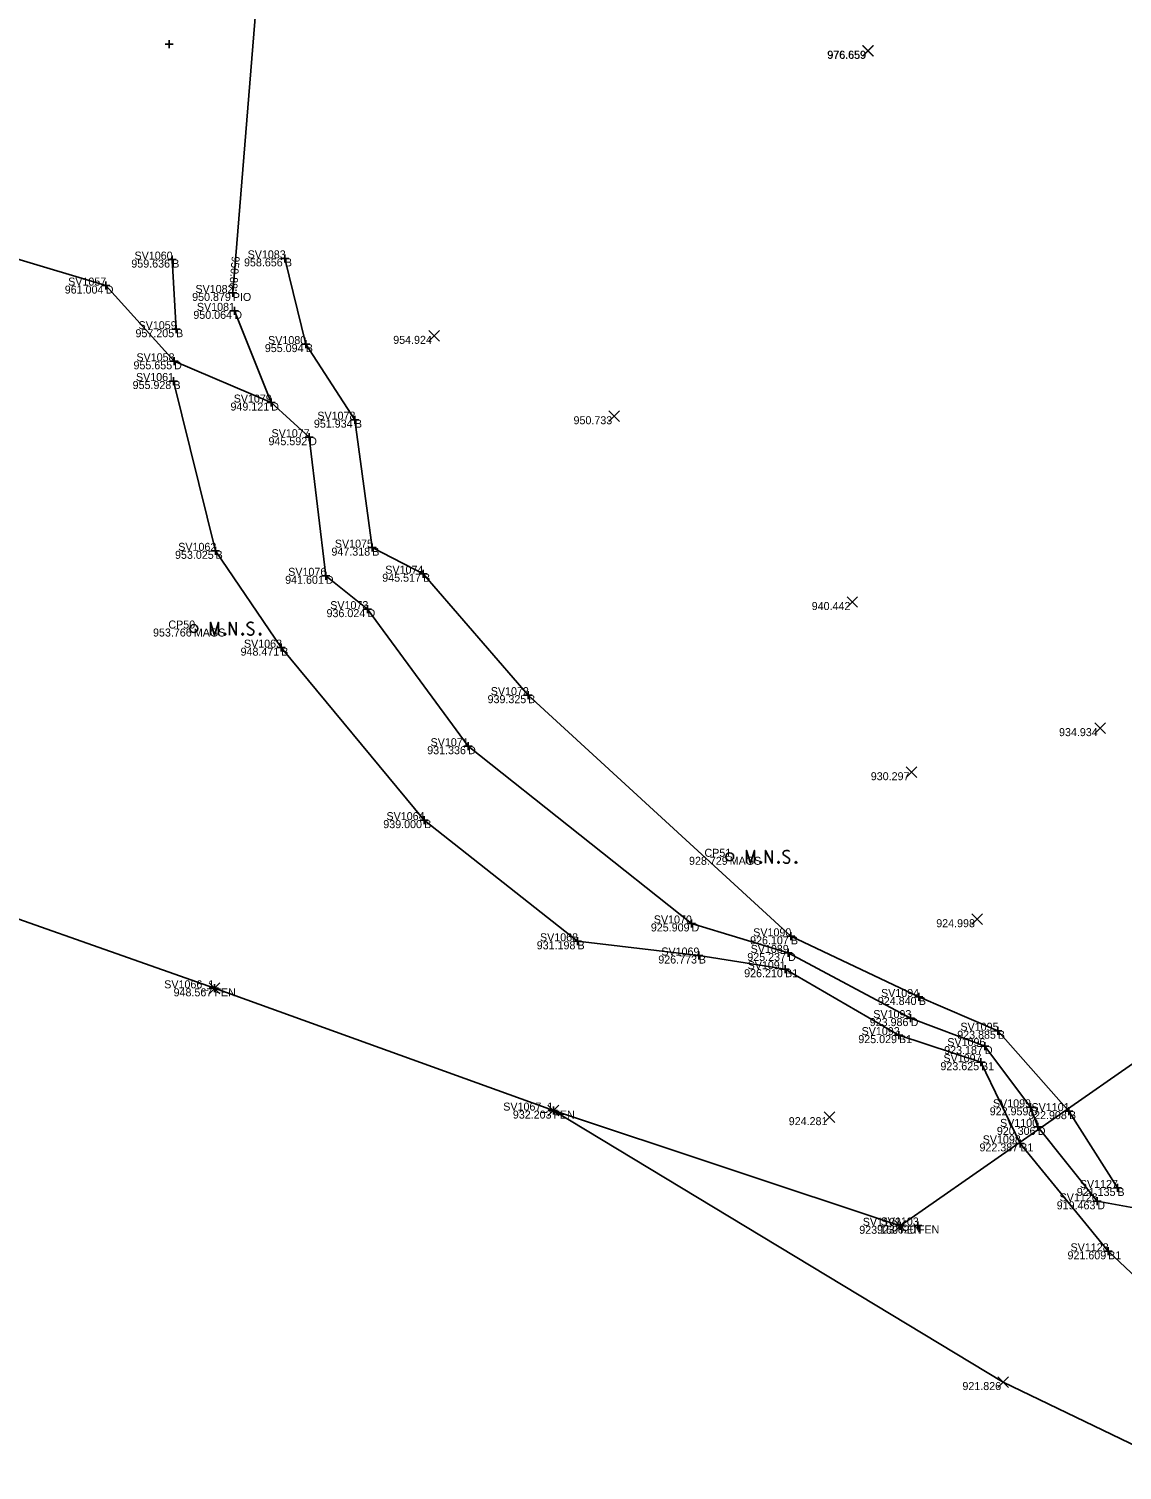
# Model space of a CAD drawing. Extents: x 2065431 to 2068157, y 709104 to 709719.
# Drawn here: x 2067117.5 to 2067254.1, y 709104.9 to 709285 of the extents above; entities that cross this region are included whole.
import ezdxf

# ---------------------------------------------------------------- set-up
doc = ezdxf.new("R2010")
doc.units = 0
for name, color, linetype in [('_CIVIL_CONSTRUCTION', 7, 'Continuous'), ('DR_X_Storm_Sewer', 7, 'Continuous'), ('DT_X_Terrain_Boundary', 7, 'Continuous'), ('RD_X_Fence', 7, 'Continuous'), ('RS_Raster1', 7, 'Continuous'), ('RW_X_CL_100_Bearings', 7, 'Continuous'), ('RW_X_CL_100_Curve_Data', 7, 'Continuous'), ('RW_X_Fee_WL', 7, 'Continuous'), ('SC_Scratch1', 7, 'Continuous'), ('SV_X_Break_Lines', 7, 'Continuous'), ('SV_X_Mon_Cells_Found', 7, 'Continuous'), ('SV_X_Text_Elevation', 7, 'Continuous'), ('SV_X_Text_Name', 7, 'Continuous')]:
    doc.layers.add(name, color=color, linetype=linetype)

msp = doc.modelspace()

# ---------------------------------------------------------------- linework, layer by layer
at = {"layer": '_CIVIL_CONSTRUCTION'}
for p, q in [((2067142.47, 709251.99), (2067143.47, 709251.99)), ((2067142.97, 709252.49), (2067142.97, 709251.49)), ((2067142.97, 709251.99), (2067142.97, 709251.99))]:
    msp.add_line(p, q, dxfattribs=at)
at = {"layer": 'DR_X_Storm_Sewer'}
msp.add_line((2067152.25, 709366.82), (2067142.97, 709251.99), dxfattribs=at)
at = {"layer": 'DT_X_Terrain_Boundary'}
msp.add_lwpolyline([(2067102.37, 709178.61), (2067140.67, 709165.08), (2067183.02, 709149.8), (2067239.23, 709115.87), (2067261.89, 709104.93), (2067274.06, 709104.86), (2067277.37, 709106.22), (2067284.73, 709107.64), (2067304.22, 709108.67), (2067329.31, 709129.97), (2067346.3, 709160.09), (2067342.01, 709185.45), (2067370.56, 709268.21), (2067411.97, 709264.45), (2067464.57, 709259.36), (2067538.62, 709266.34)], dxfattribs=at)
at = {"layer": 'RD_X_Fence'}
msp.add_line((2067226.35, 709135.4), (2067267.15, 709163.89), dxfattribs=at)
msp.add_lwpolyline([(2067064.4, 709192.69), (2067102.37, 709178.61), (2067140.67, 709165.08), (2067183.02, 709149.8), (2067226.35, 709135.4)], dxfattribs=at)
at = {"layer": 'RS_Raster1'}
for p, q in [((2067134.5, 709283.08), (2067135.5, 709283.08)), ((2067135, 709283.58), (2067135, 709282.58)), ((2067135, 709283.08), (2067135, 709283.08)), ((2067134.9, 709256.16), (2067135.9, 709256.16)), ((2067135.4, 709256.66), (2067135.4, 709255.66)), ((2067135.4, 709256.16), (2067135.4, 709256.16)), ((2067148.98, 709256.31), (2067149.98, 709256.31)), ((2067149.48, 709256.81), (2067149.48, 709255.81)), ((2067149.48, 709256.31), (2067149.48, 709256.31)), ((2067127.09, 709253.41), (2067127.09, 709252.41)), ((2067126.59, 709252.91), (2067127.59, 709252.91)), ((2067127.09, 709252.91), (2067127.09, 709252.91)), ((2067142.66, 709249.75), (2067143.66, 709249.75)), ((2067143.16, 709250.25), (2067143.16, 709249.25)), ((2067143.16, 709249.75), (2067143.16, 709249.75)), ((2067135.88, 709247.96), (2067135.88, 709246.96)), ((2067135.38, 709247.46), (2067136.38, 709247.46)), ((2067135.88, 709247.46), (2067135.88, 709247.46)), ((2067151.59, 709245.6), (2067152.59, 709245.6)), ((2067152.09, 709246.1), (2067152.09, 709245.1)), ((2067152.09, 709245.6), (2067152.09, 709245.6)), ((2067135.13, 709243.45), (2067136.13, 709243.45)), ((2067135.63, 709243.95), (2067135.63, 709242.95)), ((2067135.63, 709243.45), (2067135.63, 709243.45)), ((2067135.05, 709240.98), (2067136.05, 709240.98)), ((2067135.55, 709241.48), (2067135.55, 709240.48)), ((2067135.55, 709240.98), (2067135.55, 709240.98)), ((2067147.26, 709238.29), (2067148.26, 709238.29)), ((2067147.76, 709238.79), (2067147.76, 709237.79)), ((2067147.76, 709238.29), (2067147.76, 709238.29)), ((2067157.72, 709236.15), (2067158.72, 709236.15)), ((2067158.22, 709236.65), (2067158.22, 709235.65)), ((2067158.22, 709236.15), (2067158.22, 709236.15)), ((2067152.01, 709233.96), (2067153.01, 709233.96)), ((2067152.51, 709234.46), (2067152.51, 709233.46)), ((2067152.51, 709233.96), (2067152.51, 709233.96)), ((2067140.32, 709219.76), (2067141.32, 709219.76)), ((2067140.82, 709220.26), (2067140.82, 709219.26)), ((2067140.82, 709219.76), (2067140.82, 709219.76)), ((2067159.89, 709220.16), (2067160.89, 709220.16)), ((2067160.39, 709220.66), (2067160.39, 709219.66)), ((2067160.39, 709220.16), (2067160.39, 709220.16)), ((2067166.74, 709217.4), (2067166.74, 709216.4)), ((2067154.09, 709216.64), (2067155.09, 709216.64)), ((2067154.59, 709217.14), (2067154.59, 709216.14)), ((2067154.59, 709216.64), (2067154.59, 709216.64)), ((2067166.24, 709216.9), (2067167.24, 709216.9)), ((2067166.74, 709216.9), (2067166.74, 709216.9)), ((2067159.3, 709212.47), (2067160.3, 709212.47)), ((2067159.8, 709212.97), (2067159.8, 709211.97)), ((2067159.8, 709212.47), (2067159.8, 709212.47)), ((2067148.52, 709207.66), (2067149.52, 709207.66)), ((2067149.02, 709208.16), (2067149.02, 709207.16)), ((2067149.02, 709207.66), (2067149.02, 709207.66)), ((2067179.37, 709201.72), (2067180.37, 709201.72)), ((2067179.87, 709202.22), (2067179.87, 709201.22)), ((2067179.87, 709201.72), (2067179.87, 709201.72)), ((2067172.36, 709195.84), (2067172.36, 709194.84)), ((2067171.86, 709195.34), (2067172.86, 709195.34)), ((2067172.36, 709195.34), (2067172.36, 709195.34)), ((2067166.39, 709186.1), (2067167.39, 709186.1)), ((2067166.89, 709186.6), (2067166.89, 709185.6)), ((2067166.89, 709186.1), (2067166.89, 709186.1)), ((2067199.78, 709173.19), (2067200.78, 709173.19)), ((2067200.28, 709173.69), (2067200.28, 709172.69)), ((2067200.28, 709173.19), (2067200.28, 709173.19)), ((2067185.54, 709170.96), (2067186.54, 709170.96)), ((2067186.04, 709171.46), (2067186.04, 709170.46)), ((2067186.04, 709170.96), (2067186.04, 709170.96)), ((2067212.2, 709171.58), (2067213.2, 709171.58)), ((2067212.7, 709172.08), (2067212.7, 709171.08)), ((2067212.7, 709171.58), (2067212.7, 709171.58)), ((2067200.69, 709169.18), (2067201.69, 709169.18)), ((2067201.19, 709169.68), (2067201.19, 709168.68)), ((2067201.19, 709169.18), (2067201.19, 709169.18)), ((2067211.85, 709169.5), (2067212.85, 709169.5)), ((2067212.35, 709170), (2067212.35, 709169)), ((2067212.35, 709169.5), (2067212.35, 709169.5)), ((2067211.47, 709167.47), (2067212.47, 709167.47)), ((2067211.97, 709167.97), (2067211.97, 709166.97)), ((2067211.97, 709167.47), (2067211.97, 709167.47)), ((2067140.17, 709165.08), (2067141.17, 709165.08)), ((2067140.67, 709165.58), (2067140.67, 709164.58)), ((2067140.67, 709165.08), (2067140.67, 709165.08)), ((2067228.18, 709164), (2067229.18, 709164)), ((2067228.68, 709164.5), (2067228.68, 709163.5)), ((2067228.68, 709164), (2067228.68, 709164)), ((2067227.66, 709161.86), (2067227.66, 709160.86)), ((2067226.2, 709159.73), (2067226.2, 709158.73)), ((2067227.16, 709161.36), (2067228.16, 709161.36)), ((2067227.66, 709161.36), (2067227.66, 709161.36)), ((2067238.05, 709159.78), (2067239.05, 709159.78)), ((2067238.55, 709160.28), (2067238.55, 709159.28)), ((2067238.55, 709159.78), (2067238.55, 709159.78)), ((2067225.7, 709159.23), (2067226.7, 709159.23)), ((2067226.2, 709159.23), (2067226.2, 709159.23)), ((2067236.44, 709157.86), (2067237.44, 709157.86)), ((2067236.94, 709158.36), (2067236.94, 709157.36)), ((2067236.94, 709157.86), (2067236.94, 709157.86)), ((2067236.45, 709156.35), (2067236.45, 709155.35)), ((2067235.95, 709155.85), (2067236.95, 709155.85)), ((2067236.45, 709155.85), (2067236.45, 709155.85)), ((2067242.62, 709150.71), (2067242.62, 709149.71)), ((2067182.52, 709149.8), (2067183.52, 709149.8)), ((2067183.02, 709150.3), (2067183.02, 709149.3)), ((2067183.02, 709149.8), (2067183.02, 709149.8)), ((2067242.12, 709150.21), (2067243.12, 709150.21)), ((2067242.62, 709150.21), (2067242.62, 709150.21)), ((2067246.94, 709149.73), (2067247.94, 709149.73)), ((2067247.44, 709150.23), (2067247.44, 709149.23)), ((2067247.44, 709149.73), (2067247.44, 709149.73)), ((2067243.04, 709147.76), (2067244.04, 709147.76)), ((2067243.54, 709148.26), (2067243.54, 709147.26)), ((2067243.54, 709147.76), (2067243.54, 709147.76)), ((2067240.86, 709145.7), (2067241.86, 709145.7)), ((2067241.36, 709146.2), (2067241.36, 709145.2)), ((2067241.36, 709145.7), (2067241.36, 709145.7)), ((2067252.99, 709140.13), (2067253.99, 709140.13)), ((2067253.49, 709140.63), (2067253.49, 709139.63)), ((2067253.49, 709140.13), (2067253.49, 709140.13)), ((2067250.48, 709138.46), (2067251.48, 709138.46)), ((2067250.98, 709138.96), (2067250.98, 709137.96)), ((2067250.98, 709138.46), (2067250.98, 709138.46)), ((2067225.85, 709135.4), (2067226.85, 709135.4)), ((2067225.85, 709135.4), (2067226.85, 709135.4)), ((2067226.35, 709135.9), (2067226.35, 709134.9)), ((2067226.35, 709135.9), (2067226.35, 709134.9)), ((2067226.35, 709135.4), (2067226.35, 709135.4)), ((2067226.35, 709135.4), (2067226.35, 709135.4)), ((2067228.07, 709135.44), (2067229.07, 709135.44)), ((2067228.57, 709135.94), (2067228.57, 709134.94)), ((2067228.57, 709135.44), (2067228.57, 709135.44)), ((2067252.34, 709132.71), (2067252.34, 709131.71)), ((2067251.84, 709132.21), (2067252.84, 709132.21)), ((2067252.34, 709132.21), (2067252.34, 709132.21))]:
    msp.add_line(p, q, dxfattribs=at)
at = {"layer": 'RW_X_CL_100_Bearings'}
for p, q in [((2067221.65, 709281.6), (2067222.98, 709282.93)), ((2067221.65, 709282.93), (2067222.98, 709281.6)), ((2067221.69, 709281.57), (2067223.02, 709282.91)), ((2067221.69, 709282.91), (2067223.02, 709281.57)), ((2067167.46, 709245.96), (2067168.8, 709247.3)), ((2067167.46, 709247.3), (2067168.8, 709245.96)), ((2067189.94, 709235.91), (2067191.27, 709237.25)), ((2067189.94, 709237.25), (2067191.27, 709235.91)), ((2067219.71, 709212.7), (2067221.04, 709214.03)), ((2067219.71, 709214.03), (2067221.04, 709212.7)), ((2067250.66, 709196.93), (2067251.99, 709198.27)), ((2067250.66, 709198.27), (2067251.99, 709196.93)), ((2067227.11, 709191.42), (2067228.44, 709192.75)), ((2067227.11, 709192.75), (2067228.44, 709191.42)), ((2067235.29, 709173.05), (2067236.63, 709174.39)), ((2067235.29, 709174.39), (2067236.63, 709173.05)), ((2067140, 709164.41), (2067141.33, 709165.75)), ((2067140, 709165.75), (2067141.33, 709164.41)), ((2067182.35, 709149.13), (2067183.69, 709150.47)), ((2067182.35, 709150.47), (2067183.69, 709149.13)), ((2067216.84, 709148.31), (2067218.17, 709149.65)), ((2067216.84, 709149.65), (2067218.17, 709148.31)), ((2067225.69, 709134.73), (2067227.02, 709136.06)), ((2067225.69, 709136.06), (2067227.02, 709134.73)), ((2067238.57, 709115.2), (2067239.9, 709116.53)), ((2067238.57, 709116.53), (2067239.9, 709115.2))]:
    msp.add_line(p, q, dxfattribs=at)
at = {"layer": 'RW_X_CL_100_Curve_Data'}
for points in [[(2067140.19, 709209.24), (2067140.19, 709210.84), (2067140.7, 709209.24), (2067141.18, 709210.84), (2067141.18, 709209.24)], [(2067142.56, 709209.24), (2067142.56, 709210.84), (2067143.39, 709209.24), (2067143.39, 709210.84)], [(2067145.54, 709210.73), (2067145.51, 709210.76), (2067145.48, 709210.78), (2067145.38, 709210.82), (2067145.26, 709210.84), (2067145.17, 709210.84), (2067145.14, 709210.84), (2067145, 709210.81), (2067144.88, 709210.73), (2067144.8, 709210.63), (2067144.78, 709210.53), (2067144.78, 709210.45), (2067144.8, 709210.35), (2067144.89, 709210.26), (2067145.49, 709209.89), (2067145.55, 709209.84), (2067145.57, 709209.79), (2067145.59, 709209.71), (2067145.59, 709209.64), (2067145.58, 709209.56), (2067145.57, 709209.51), (2067145.55, 709209.45), (2067145.53, 709209.4), (2067145.5, 709209.36), (2067145.47, 709209.32), (2067145.44, 709209.29), (2067145.39, 709209.27), (2067145.36, 709209.26), (2067145.26, 709209.24), (2067145.11, 709209.24), (2067145.01, 709209.27), (2067144.86, 709209.36), (2067144.78, 709209.43)], [(2067141.95, 709209.46), (2067142.01, 709209.46), (2067142.04, 709209.43), (2067142.08, 709209.38), (2067142.08, 709209.32), (2067142.04, 709209.27), (2067142.01, 709209.24), (2067141.95, 709209.24), (2067141.92, 709209.27), (2067141.89, 709209.32), (2067141.89, 709209.38), (2067141.92, 709209.43), (2067141.95, 709209.46)], [(2067144.17, 709209.46), (2067144.22, 709209.46), (2067144.26, 709209.43), (2067144.29, 709209.38), (2067144.29, 709209.32), (2067144.26, 709209.27), (2067144.22, 709209.24), (2067144.17, 709209.24), (2067144.14, 709209.27), (2067144.1, 709209.32), (2067144.1, 709209.38), (2067144.14, 709209.43), (2067144.17, 709209.46)], [(2067146.35, 709209.46), (2067146.41, 709209.46), (2067146.44, 709209.43), (2067146.47, 709209.38), (2067146.47, 709209.32), (2067146.44, 709209.27), (2067146.41, 709209.24), (2067146.35, 709209.24), (2067146.32, 709209.27), (2067146.29, 709209.32), (2067146.29, 709209.38), (2067146.32, 709209.43), (2067146.35, 709209.46)], [(2067207.14, 709180.72), (2067207.14, 709182.32), (2067207.65, 709180.72), (2067208.13, 709182.32), (2067208.13, 709180.72)], [(2067209.51, 709180.72), (2067209.51, 709182.32), (2067210.34, 709180.72), (2067210.34, 709182.32)], [(2067212.49, 709182.2), (2067212.47, 709182.23), (2067212.43, 709182.25), (2067212.33, 709182.29), (2067212.21, 709182.32), (2067212.12, 709182.32), (2067212.09, 709182.32), (2067211.95, 709182.28), (2067211.83, 709182.2), (2067211.75, 709182.1), (2067211.73, 709182), (2067211.73, 709181.92), (2067211.75, 709181.82), (2067211.84, 709181.74), (2067212.44, 709181.36), (2067212.5, 709181.31), (2067212.52, 709181.26), (2067212.54, 709181.18), (2067212.54, 709181.11), (2067212.53, 709181.03), (2067212.52, 709180.98), (2067212.5, 709180.92), (2067212.48, 709180.87), (2067212.46, 709180.83), (2067212.42, 709180.79), (2067212.39, 709180.77), (2067212.35, 709180.74), (2067212.31, 709180.73), (2067212.21, 709180.72), (2067212.06, 709180.72), (2067211.96, 709180.74), (2067211.82, 709180.83), (2067211.73, 709180.9)], [(2067208.91, 709180.93), (2067208.96, 709180.93), (2067208.99, 709180.9), (2067209.03, 709180.85), (2067209.03, 709180.79), (2067208.99, 709180.74), (2067208.96, 709180.72), (2067208.91, 709180.72), (2067208.87, 709180.74), (2067208.84, 709180.79), (2067208.84, 709180.85), (2067208.87, 709180.9), (2067208.91, 709180.93)], [(2067211.12, 709180.93), (2067211.18, 709180.93), (2067211.21, 709180.9), (2067211.24, 709180.85), (2067211.24, 709180.79), (2067211.21, 709180.74), (2067211.18, 709180.72), (2067211.12, 709180.72), (2067211.09, 709180.74), (2067211.06, 709180.79), (2067211.06, 709180.85), (2067211.09, 709180.9), (2067211.12, 709180.93)], [(2067213.3, 709180.93), (2067213.36, 709180.93), (2067213.39, 709180.9), (2067213.43, 709180.85), (2067213.43, 709180.79), (2067213.39, 709180.74), (2067213.36, 709180.72), (2067213.3, 709180.72), (2067213.27, 709180.74), (2067213.24, 709180.79), (2067213.24, 709180.85), (2067213.27, 709180.9), (2067213.3, 709180.93)]]:
    msp.add_lwpolyline(points, dxfattribs=at)
for centre in [(2067138.1, 709210.04), (2067205.05, 709181.52)]:
    msp.add_circle(centre, 0.497, dxfattribs=at)
at = {"layer": 'RW_X_Fee_WL'}
for points in [[(2067059.4, 709283.92), (2067099.57, 709266.25), (2067115.56, 709256.37), (2067127.09, 709252.91)], [(2067127.09, 709252.91), (2067135.63, 709243.45), (2067147.76, 709238.29)], [(2067212.35, 709169.5), (2067200.28, 709173.19), (2067172.36, 709195.34), (2067159.8, 709212.47), (2067154.59, 709216.64), (2067152.51, 709233.96), (2067147.76, 709238.29), (2067143.16, 709249.75)], [(2067212.35, 709169.5), (2067227.66, 709161.36), (2067236.94, 709157.86), (2067242.62, 709150.21), (2067243.54, 709147.76), (2067250.98, 709138.46), (2067267.91, 709135.38), (2067272.56, 709134.83)]]:
    msp.add_lwpolyline(points, dxfattribs=at)
at = {"layer": 'SV_X_Break_Lines'}
for points in [[(2067135.88, 709247.46), (2067135.4, 709256.16)], [(2067179.87, 709201.72), (2067166.74, 709216.9), (2067160.39, 709220.16), (2067158.22, 709236.15), (2067152.09, 709245.6), (2067149.48, 709256.31)], [(2067135.55, 709240.98), (2067140.82, 709219.76), (2067149.02, 709207.66), (2067166.89, 709186.1), (2067186.04, 709170.96), (2067201.19, 709169.18), (2067211.97, 709167.47)], [(2067179.87, 709201.72), (2067212.7, 709171.58), (2067228.68, 709164), (2067238.55, 709159.78), (2067247.44, 709149.73), (2067253.49, 709140.13)], [(2067211.97, 709167.47), (2067226.2, 709159.23), (2067236.45, 709155.85), (2067241.36, 709145.7), (2067252.34, 709132.21), (2067260.18, 709124.85), (2067261.89, 709104.93)]]:
    msp.add_lwpolyline(points, dxfattribs=at)

# ---------------------------------------------------------------- texts
at = {"layer": 'SC_Scratch1'}
msp.add_text("950.88'", height=1, rotation=265.3805, dxfattribs=at).set_placement((2067142.85, 709256.61))
at = {"layer": 'SV_X_Mon_Cells_Found'}
for s, p in [('SV1060', (2067130.69, 709256.16)), ('SV1083', (2067144.82, 709256.31)), ('SV1057', (2067122.4, 709252.91)), ('SV1082', (2067138.3, 709251.99)), ('SV1081', (2067138.48, 709249.75)), ('SV1059', (2067131.19, 709247.46)), ('SV1080', (2067147.38, 709245.6)), ('SV1058', (2067130.93, 709243.45)), ('SV1061', (2067130.87, 709240.98)), ('SV1079', (2067143.08, 709238.29)), ('SV1078', (2067153.53, 709236.15)), ('SV1077', (2067147.81, 709233.96)), ('SV1075', (2067155.72, 709220.16)), ('SV1062', (2067136.15, 709219.76)), ('SV1076', (2067149.89, 709216.64)), ('SV1074', (2067162.02, 709216.9)), ('SV1073', (2067155.14, 709212.47)), ('CP50', (2067134.92, 709210.05)), ('SV1063', (2067144.36, 709207.66)), ('SV1072', (2067175.2, 709201.72)), ('SV1071', (2067167.68, 709195.34)), ('SV1064', (2067162.17, 709186.1)), ('CP51', (2067201.9, 709181.52)), ('SV1070', (2067195.57, 709173.19)), ('SV1090', (2067207.99, 709171.58)), ('SV1068', (2067181.35, 709170.96)), ('SV1089', (2067207.67, 709169.5)), ('SV1069', (2067196.51, 709169.18)), ('SV1091', (2067207.29, 709167.47)), ('SV1066_1', (2067134.4, 709165.08)), ('SV1094', (2067223.96, 709164)), ('SV1093', (2067222.99, 709161.36)), ('SV1092', (2067221.53, 709159.23)), ('SV1095', (2067233.88, 709159.78)), ('SV1096', (2067232.24, 709157.86)), ('SV1097', (2067231.76, 709155.85)), ('SV1067_1', (2067176.76, 709149.8)), ('SV1099', (2067237.94, 709150.21)), ('SV1101', (2067242.76, 709149.73)), ('SV1100', (2067238.83, 709147.76)), ('SV1098', (2067236.66, 709145.7)), ('SV1127', (2067248.8, 709140.13)), ('SV1126', (2067246.27, 709138.46)), ('SV1102', (2067221.68, 709135.4)), ('SV1103', (2067223.91, 709135.44)), ('SV1128', (2067247.64, 709132.21))]:
    msp.add_text(s, height=1, dxfattribs=at).set_placement(p)
at = {"layer": 'SV_X_Text_Elevation'}
for s, p in [('B', (2067135.4, 709255.16)), ('B', (2067149.48, 709255.31)), ('D', (2067127.09, 709251.91)), ('PIO', (2067142.97, 709250.99)), ('D', (2067143.16, 709248.75)), ('B', (2067135.88, 709246.46)), ('B', (2067152.09, 709244.6)), ('D', (2067135.63, 709242.45)), ('B', (2067135.55, 709239.98)), ('D', (2067147.76, 709237.29)), ('B', (2067158.22, 709235.15)), ('D', (2067152.51, 709232.96)), ('B', (2067140.82, 709218.76)), ('B', (2067160.39, 709219.16)), ('D', (2067154.59, 709215.64)), ('B', (2067166.74, 709215.9)), ('D', (2067159.8, 709211.47)), ('MAGS', (2067138.1, 709209.05)), ('B', (2067149.02, 709206.66)), ('B', (2067179.87, 709200.72)), ('D', (2067172.36, 709194.34)), ('B', (2067166.89, 709185.1)), ('MAGS', (2067205.05, 709180.52)), ('D', (2067200.28, 709172.19)), ('B', (2067186.04, 709169.96)), ('B', (2067212.7, 709170.58)), ('B', (2067201.19, 709168.18)), ('D', (2067212.35, 709168.5)), ('B1', (2067211.97, 709166.47)), ('FEN', (2067140.67, 709164.08)), ('B', (2067228.68, 709163)), ('D', (2067227.66, 709160.36)), ('B', (2067238.55, 709158.78)), ('B1', (2067226.2, 709158.23)), ('D', (2067236.94, 709156.86)), ('B1', (2067236.45, 709154.85)), ('FEN', (2067183.02, 709148.8)), ('D', (2067242.62, 709149.21)), ('B', (2067247.44, 709148.73)), ('D', (2067243.54, 709146.76)), ('B1', (2067241.36, 709144.7)), ('B', (2067253.49, 709139.13)), ('D', (2067250.98, 709137.46)), ('FEN', (2067226.35, 709134.4)), ('FEN', (2067228.57, 709134.44)), ('B1', (2067252.34, 709131.21))]:
    msp.add_text(s, height=1, dxfattribs=at).set_placement(p)
at = {"layer": 'SV_X_Text_Name'}
for s, p in [('976.659', (2067217.23, 709281.27)), ('976.659', (2067217.27, 709281.24)), ('959.636', (2067130.29, 709255.16)), ('958.656', (2067144.37, 709255.31)), ('961.004', (2067121.97, 709251.91)), ('950.879', (2067137.89, 709250.99)), ('950.064', (2067138.04, 709248.75)), ('957.205', (2067130.81, 709246.46)), ('954.924', (2067163.01, 709245.63)), ('955.094', (2067146.97, 709244.6)), ('955.655', (2067130.56, 709242.45)), ('955.928', (2067130.45, 709239.98)), ('949.121', (2067142.68, 709237.29)), ('951.934', (2067153.1, 709235.15)), ('950.733', (2067185.54, 709235.58)), ('945.592', (2067147.43, 709232.96)), ('953.025', (2067135.75, 709218.76)), ('947.318', (2067155.29, 709219.16)), ('941.601', (2067149.51, 709215.64)), ('945.517', (2067161.64, 709215.9)), ('936.024', (2067154.68, 709211.47)), ('940.442', (2067215.3, 709212.36)), ('953.766', (2067133, 709209.05)), ('948.471', (2067143.94, 709206.66)), ('939.325', (2067174.8, 709200.72)), ('934.934', (2067246.2, 709196.6)), ('931.336', (2067167.26, 709194.34)), ('930.297', (2067222.68, 709191.09)), ('939.000', (2067161.77, 709185.1)), ('928.729', (2067199.97, 709180.52)), ('925.909', (2067195.2, 709172.19)), ('924.998', (2067230.86, 709172.72)), ('931.198', (2067180.94, 709169.96)), ('926.107', (2067207.6, 709170.58)), ('926.773', (2067196.13, 709168.18)), ('925.237', (2067207.25, 709168.5)), ('926.210', (2067206.86, 709166.47)), ('948.567', (2067135.57, 709164.08)), ('948.567', (2067135.57, 709164.08)), ('924.840', (2067223.56, 709163)), ('923.986', (2067222.55, 709160.36)), ('923.885', (2067233.48, 709158.78)), ('925.029', (2067221.12, 709158.23)), ('923.187', (2067231.85, 709156.86)), ('923.625', (2067231.38, 709154.85)), ('932.203', (2067177.96, 709148.8)), ('932.203', (2067177.96, 709148.8)), ('924.281', (2067212.43, 709147.98)), ('922.959', (2067237.54, 709149.21)), ('922.908', (2067242.34, 709148.73)), ('920.306', (2067238.43, 709146.76)), ('922.387', (2067236.26, 709144.7)), ('921.135', (2067248.42, 709139.13)), ('919.463', (2067245.91, 709137.46)), ('923.160', (2067221.24, 709134.4)), ('923.160', (2067221.24, 709134.4)), ('923.020', (2067223.46, 709134.44)), ('921.609', (2067247.26, 709131.21)), ('921.826', (2067234.13, 709114.87))]:
    msp.add_text(s, height=1, dxfattribs=at).set_placement(p)

doc.saveas('drawing.dxf')
